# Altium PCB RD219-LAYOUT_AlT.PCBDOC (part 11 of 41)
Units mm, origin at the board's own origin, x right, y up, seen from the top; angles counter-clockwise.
Board outline 209.75 x 159.97 mm, 2 copper layers (TOP, BOTTOM), stack 0 mm thick; 398 components, 199 nets, 1469 pads, 0 vias.
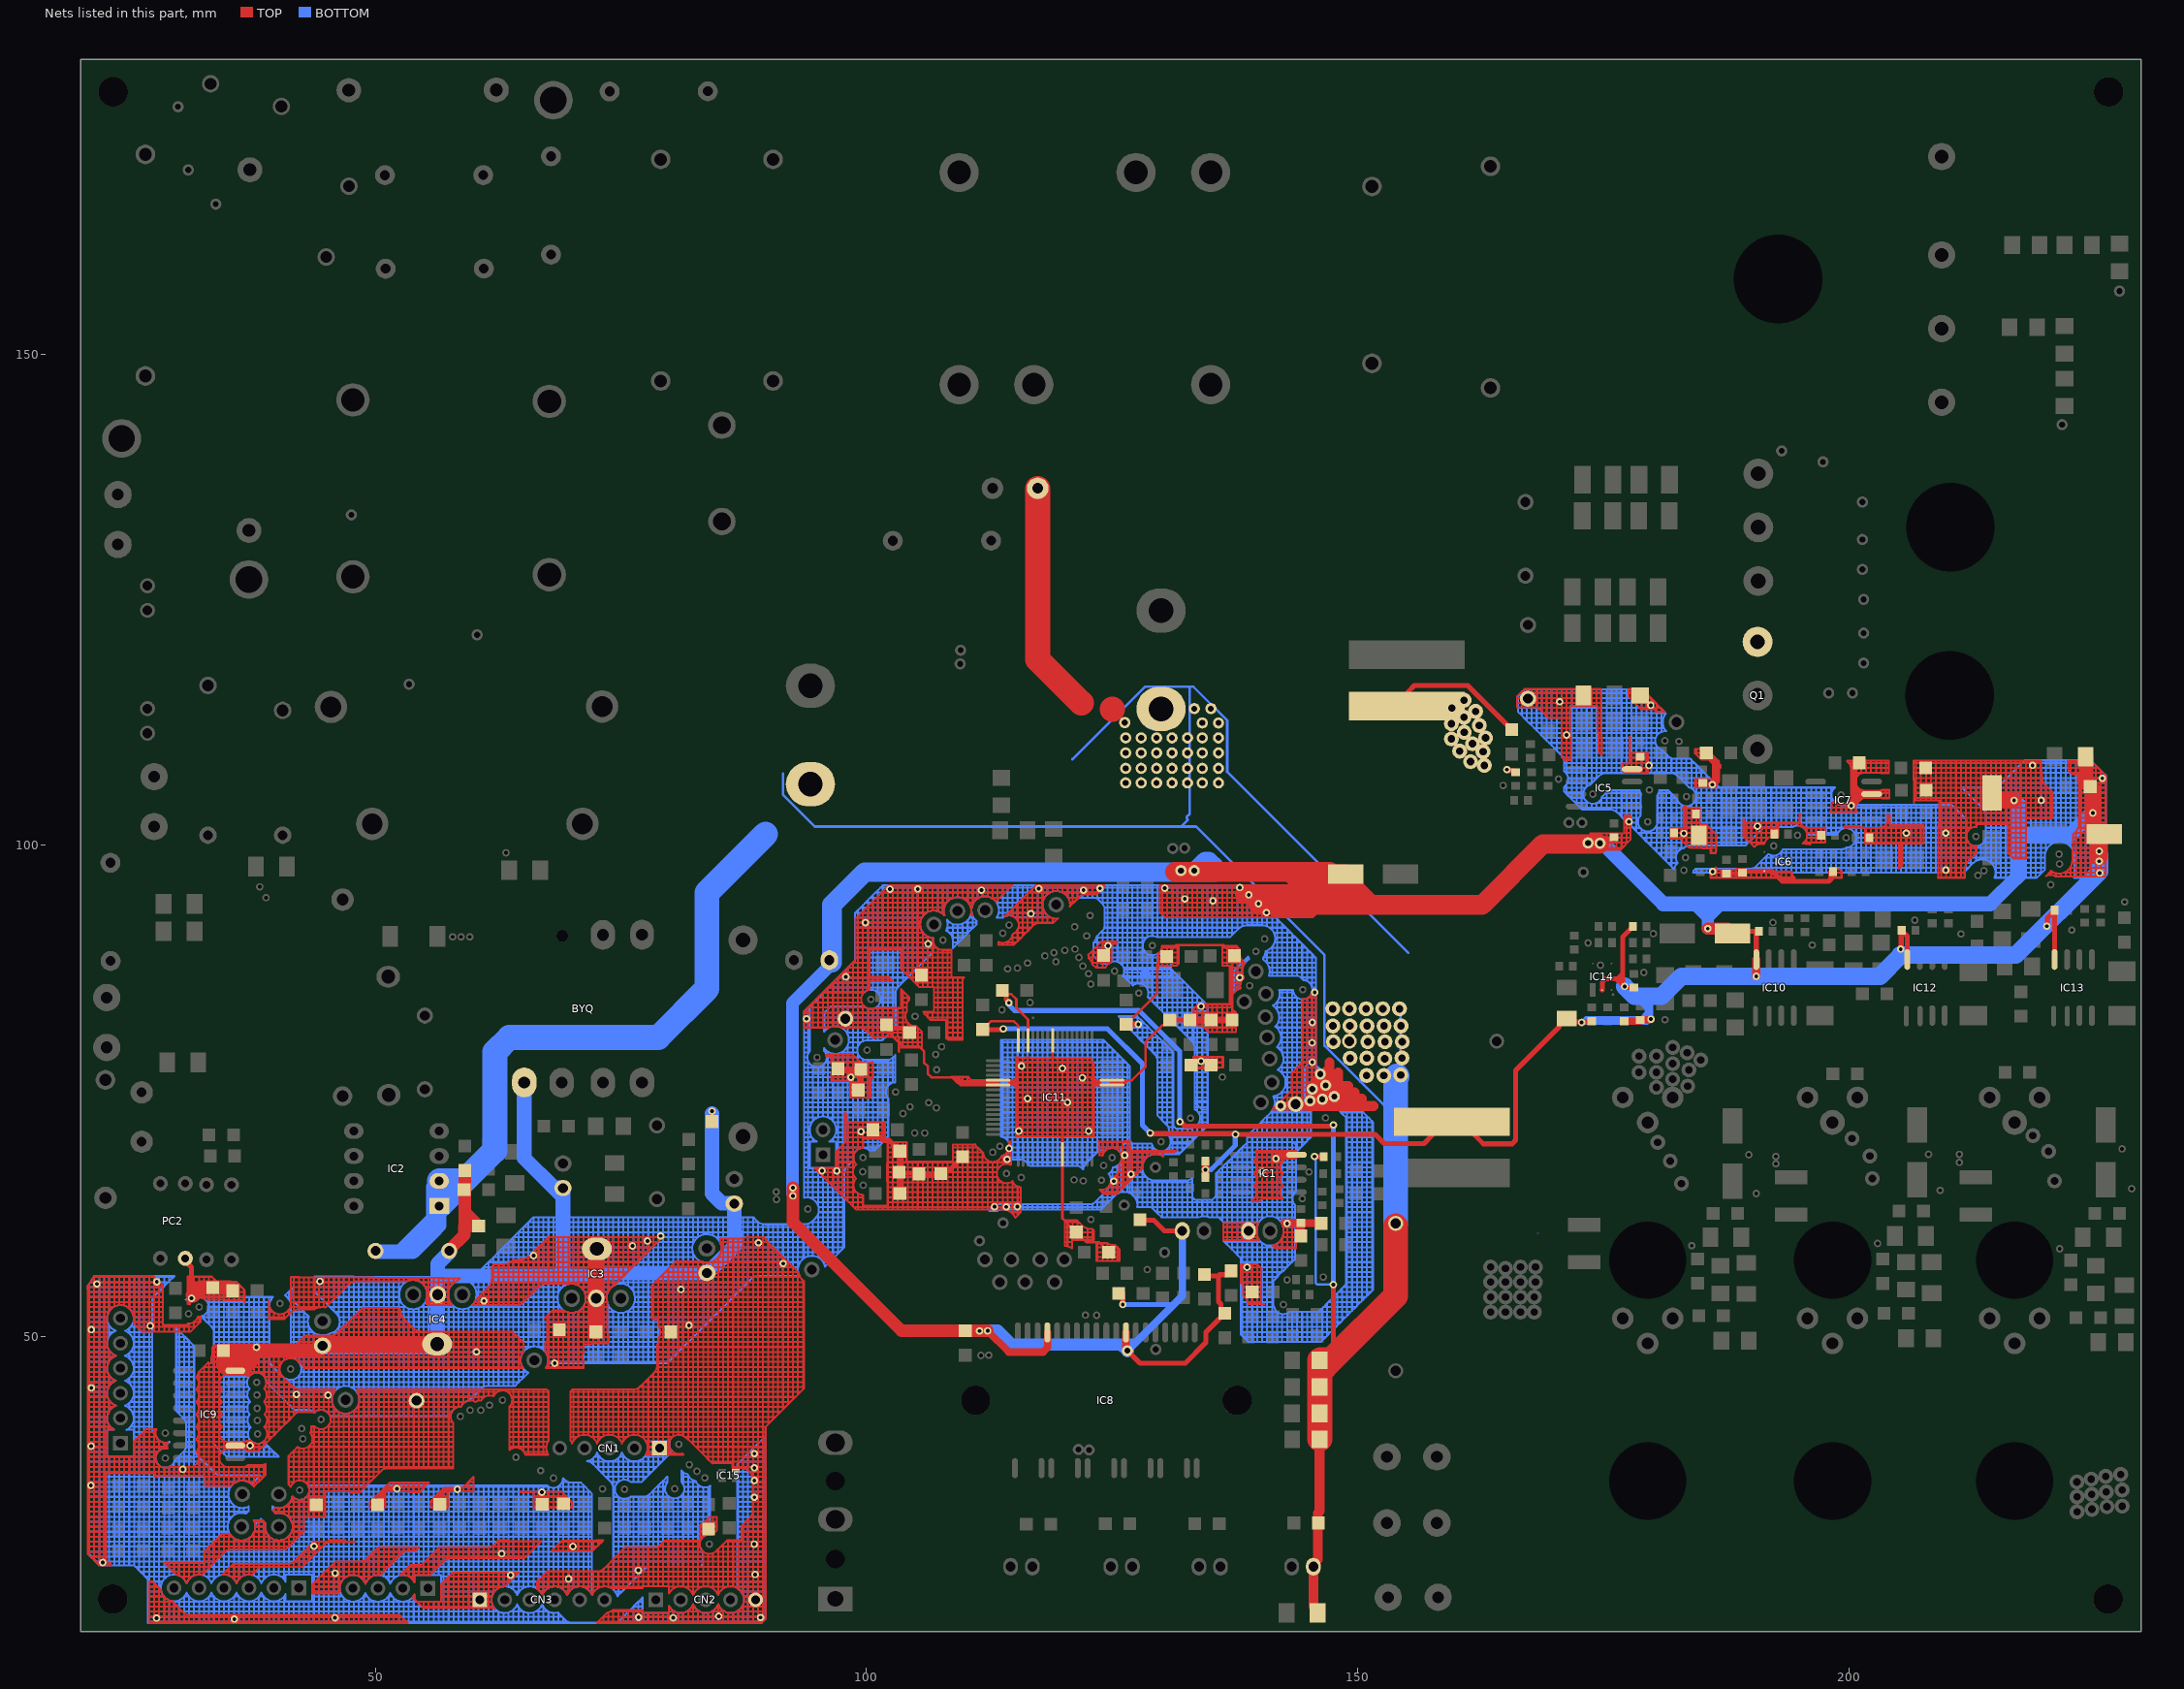
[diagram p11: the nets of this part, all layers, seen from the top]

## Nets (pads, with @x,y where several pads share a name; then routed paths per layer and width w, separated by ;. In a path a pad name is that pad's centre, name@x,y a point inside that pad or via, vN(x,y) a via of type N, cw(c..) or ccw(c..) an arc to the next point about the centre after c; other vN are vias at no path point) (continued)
GND: (continued)
  TOP w0.203: 84.897,55.56 84.897,56.068 ; 84.897,55.56 85.405,55.56 ; 84.897,56.068 84.897,56.576 ; 84.897,56.068 85.405,56.068 ; 84.897,56.576 84.897,57.084 ; 84.897,56.576 85.405,56.576 ; 84.897,57.084 84.897,57.592 ; 84.897,57.084 85.405,57.084 ; 84.897,57.592 85.405,57.592 ; 84.897,57.592 84.897,58.056 ; 84.897,58.056 ccw(c83.818,58.989) 84.934,58.1 ; 84.934,58.1 85.405,58.1 ; 84.999,28.469 85.165,28.636 ; 85.095,24.064 cw(c86.167,23.241) 85.102,24.073 cw(c86.167,23.241) 85.405,24.357 ; 85.106,59.624 85.106,59.914 85.193,60.001 85.405,60.001 ; 85.106,59.624 85.405,59.624 ; 85.165,28.636 85.405,28.636 ; 85.165,28.636 85.405,28.876 ; 85.239,59.116 85.405,59.116 ; 85.405,20.889 85.405,21.016 ; 85.405,20.889 85.913,20.889 ; 85.405,21.016 85.405,21.524 ; 85.405,21.016 85.913,21.016 ; 85.405,21.524 85.913,21.524 ; 85.405,21.524 85.405,22.032 ; 85.405,22.032 85.563,22.032 ; 85.405,24.357 cw(c86.167,23.241) 85.411,24.362 cw(c86.167,23.241) 85.913,24.569 ; 85.405,24.357 85.405,24.572 ; 85.405,24.572 85.913,24.572 ; 85.405,24.572 85.405,25.08 ; 85.405,25.08 85.913,25.08 ; 85.405,25.08 85.405,25.588 ; 85.405,25.588 85.405,26.096 ; 85.405,25.588 85.913,25.588 ; 85.405,26.096 85.913,26.096 ; 85.405,26.096 85.405,26.604 ; 85.405,26.604 85.405,27.112 ; 85.405,26.604 85.913,26.604 ; 85.405,27.112 85.405,27.62 ; 85.405,27.112 85.913,27.112 ; 85.405,27.62 85.405,28.128 ; 85.405,27.62 85.913,27.62 ; 85.405,28.128 85.405,28.636 ; 85.405,28.128 85.913,28.128 ; 85.405,28.636 85.405,28.876 ; 85.405,28.636 85.913,28.636 ; 85.405,28.876 85.673,29.144 ; 85.405,37.152 85.405,37.272 ; 85.405,37.152 85.913,37.152 ; 85.405,37.272 85.405,37.78 ; 85.405,37.272 85.913,37.272 ; 85.405,37.78 85.405,38.288 ; 85.405,37.78 85.913,37.78 ; 85.405,38.288 85.405,38.796 ; 85.405,38.288 85.913,38.288 ; 85.405,38.796 85.405,39.304 ; 85.405,38.796 85.913,38.796 ; 85.405,39.304 85.405,39.812 ; 85.405,39.304 85.913,39.304 ; 85.405,39.812 85.405,40.32 ; 85.405,39.812 85.913,39.812 ; 85.405,40.32 85.405,40.828 ; 85.405,40.32 85.913,40.32 ; 85.405,40.828 85.405,41.336 ; 85.405,40.828 85.913,40.828 ; 85.405,41.336 85.405,41.844 ; 85.405,41.336 85.913,41.336 ; 85.405,41.844 85.405,42.352 ; 85.405,41.844 85.913,41.844 ; 85.405,42.352 85.405,42.86 ; 85.405,42.352 85.913,42.352 ; 85.405,42.86 85.405,43.368 ; 85.405,42.86 85.913,42.86 ; 85.405,43.368 85.405,43.876 ; 85.405,43.368 85.913,43.368 ; 85.405,43.876 85.405,44.384 ; 85.405,43.876 85.913,43.876 ; 85.405,44.384 85.405,44.892 ; 85.405,44.384 85.913,44.384 ; 85.405,44.892 85.405,45.4 ; 85.405,44.892 85.913,44.892 ; 85.405,45.4 85.405,45.908 ; 85.405,45.4 85.913,45.4 ; 85.405,45.908 85.405,46.416 ; 85.405,45.908 85.913,45.908 ; 85.405,46.416 85.405,46.924 ; 85.405,46.416 85.913,46.416 ; 85.405,46.924 85.405,47.432 ; 85.405,46.924 85.913,46.924 ; 85.405,47.432 85.405,47.94 ; 85.405,47.432 85.913,47.432 ; 85.405,47.94 85.405,48.448 ; 85.405,47.94 85.913,47.94 ; 85.405,48.448 85.405,48.956 ; 85.405,48.448 85.913,48.448 ; 85.405,48.956 85.405,49.464 ; 85.405,48.956 85.913,48.956 ; 85.405,49.464 85.405,49.972 ; 85.405,49.464 85.913,49.464 ; 85.405,49.972 85.405,50.48 ; 85.405,49.972 85.913,49.972 ; 85.405,50.48 85.405,50.988 ; 85.405,50.48 85.913,50.48 ; 85.405,50.988 85.405,51.496 ; 85.405,50.988 85.913,50.988 ; 85.405,51.496 85.405,52.004 ; 85.405,51.496 85.913,51.496 ; 85.405,52.004 85.405,52.512 ; 85.405,52.004 85.913,52.004 ; 85.405,52.512 85.405,53.02 ; 85.405,52.512 85.913,52.512 ; 85.405,53.02 85.405,53.528 ; 85.405,53.02 85.913,53.02 ; 85.405,53.528 85.405,54.036 ; 85.405,53.528 85.913,53.528 ; 85.405,54.036 85.405,54.544 ; 85.405,54.036 85.913,54.036 ; 85.405,54.544 85.405,55.052 ; 85.405,54.544 85.913,54.544 ; 85.405,55.052 85.405,55.56 ; 85.405,55.052 85.913,55.052 ; 85.405,55.56 85.405,56.068 ; 85.405,55.56 85.913,55.56 ; 85.405,56.068 85.405,56.576 ; 85.405,56.068 85.913,56.068 ; 85.405,56.576 85.405,57.084 ; 85.405,56.576 85.913,56.576 ; 85.405,57.084 85.405,57.592 ; 85.405,57.084 85.913,57.084 ; 85.405,57.592 85.405,58.1 ; 85.405,57.592 85.913,57.592 ; 85.405,58.1 85.405,58.608 ; 85.405,58.1 85.913,58.1 ; 85.405,58.608 85.405,59.116 ; 85.405,58.608 85.913,58.608 ; 85.405,59.116 85.405,59.624 ; 85.405,59.116 85.913,59.116 ; 85.405,59.624 85.405,60.001 ; 85.405,59.624 85.913,59.624 ; 85.405,60.001 85.913,60.001 ; 85.563,22.032 ccw(c86.167,23.241) 85.909,21.914 ccw(c86.167,23.241) 85.913,21.914 ; 85.673,29.144 85.913,29.144 ; 85.673,29.144 85.833,29.303 85.913,29.303 ; 85.913,20.889 85.913,21.016 ; 85.913,20.889 86.421,20.889 ; 85.913,21.016 85.913,21.524 ; 85.913,21.016 86.421,21.016 ; 85.913,21.524 86.421,21.524 ; 85.913,21.524 85.913,21.913 ; 85.913,21.914 ccw(c86.167,23.241) 86.421,21.913 ; 85.913,24.569 cw(c86.167,23.241) 85.932,24.572 ; 85.913,24.569 85.913,24.572 ; 85.913,24.572 85.913,25.08 ; 85.913,24.572 85.932,24.572 ; 85.913,25.08 86.421,25.08 ; 85.913,25.08 85.913,25.588 ; 85.913,25.588 85.913,26.096 ; 85.913,25.588 86.421,25.588 ; 85.913,26.096 85.913,26.604 ; 85.913,26.096 86.421,26.096 ; 85.913,26.604 85.913,27.112 ; 85.913,26.604 86.421,26.604 ; 85.913,27.112 85.913,27.62 ; 85.913,27.112 86.421,27.112 ; 85.913,27.62 85.913,28.128 ; 85.913,27.62 86.421,27.62 ; 85.913,28.128 85.913,28.636 ; 85.913,28.128 86.421,28.128 ; 85.913,28.636 85.913,29.144 ; 85.913,28.636 86.421,28.636 ; 85.913,29.144 85.913,29.303 ; 85.913,29.144 86.421,29.144 ; 85.913,29.303 86.421,29.303 ; 85.913,37.152 85.913,37.272 ; 85.913,37.152 86.327,37.152 86.327,36.764 ; 85.913,37.272 85.913,37.78 ; 85.913,37.272 86.421,37.272 ; 85.913,37.78 85.913,38.288 ; 85.913,37.78 86.421,37.78 ; 85.913,38.288 85.913,38.796 ; 85.913,38.288 86.421,38.288 ; 85.913,38.796 85.913,39.304 ; 85.913,38.796 86.421,38.796 ; 85.913,39.304 85.913,39.812 ; 85.913,39.304 86.421,39.304 ; 85.913,39.812 86.421,39.812 ; 85.913,39.812 85.913,40.32 ; 85.913,40.32 85.913,40.828 ; 85.913,40.32 86.421,40.32 ; 85.913,40.828 85.913,41.336 ; 85.913,40.828 86.421,40.828 ; 85.913,41.336 85.913,41.844 ; 85.913,41.336 86.421,41.336 ; 85.913,41.844 85.913,42.352 ; 85.913,41.844 86.421,41.844 ; 85.913,42.352 85.913,42.86 ; 85.913,42.352 86.421,42.352 ; 85.913,42.86 85.913,43.368 ; 85.913,42.86 86.421,42.86 ; 85.913,43.368 85.913,43.876 ; 85.913,43.368 86.421,43.368 ; 85.913,43.876 85.913,44.384 ; 85.913,43.876 86.421,43.876 ; 85.913,44.384 86.421,44.384 ; 85.913,44.384 85.913,44.892 ; 85.913,44.892 86.421,44.892 ; 85.913,44.892 85.913,45.4 ; 85.913,45.4 85.913,45.908 ; 85.913,45.4 86.421,45.4 ; 85.913,45.908 85.913,46.416 ; 85.913,45.908 86.421,45.908 ; 85.913,46.416 86.421,46.416 ; 85.913,46.416 85.913,46.924 ; 85.913,46.924 86.421,46.924 ; 85.913,46.924 85.913,47.432 ; 85.913,47.432 85.913,47.94 ; 85.913,47.432 86.421,47.432 ; 85.913,47.94 85.913,48.448 ; 85.913,47.94 86.421,47.94 ; 85.913,48.448 85.913,48.956 ; 85.913,48.448 86.421,48.448 ; 85.913,48.956 85.913,49.464 ; 85.913,48.956 86.421,48.956 ; 85.913,49.464 85.913,49.972 ; 85.913,49.464 86.421,49.464 ; 85.913,49.972 86.421,49.972 ; 85.913,49.972 85.913,50.48 ; 85.913,50.48 85.913,50.988 ; 85.913,50.48 86.421,50.48 ; 85.913,50.988 86.421,50.988 ; 85.913,50.988 85.913,51.496 ; 85.913,51.496 85.913,52.004 ; 85.913,51.496 86.421,51.496 ; 85.913,52.004 86.421,52.004 ; 85.913,52.004 85.913,52.512 ; 85.913,52.512 85.913,53.02 ; 85.913,52.512 86.421,52.512 ; 85.913,53.02 86.421,53.02 ; 85.913,53.02 85.913,53.528 ; 85.913,53.528 85.913,54.036 ; 85.913,53.528 86.421,53.528 ; 85.913,54.036 85.913,54.544 ; 85.913,54.036 86.421,54.036 ; 85.913,54.544 85.913,55.052 ; 85.913,54.544 86.421,54.544 ; 85.913,55.052 86.421,55.052 ; 85.913,55.052 85.913,55.56 ; 85.913,55.56 86.421,55.56 ; 85.913,55.56 85.913,56.068 ; 85.913,56.068 85.913,56.576 ; 85.913,56.068 86.421,56.068 ; 85.913,56.576 86.421,56.576 ; 85.913,56.576 85.913,57.084 ; 85.913,57.084 85.913,57.592 ; 85.913,57.084 86.421,57.084 ; 85.913,57.592 85.913,58.1 ; 85.913,57.592 86.421,57.592 ; 85.913,58.1 85.913,58.608 ; 85.913,58.1 86.421,58.1 ; 85.913,58.608 85.913,59.116 ; 85.913,58.608 86.421,58.608 ; 85.913,59.116 86.421,59.116 ; 85.913,59.116 85.913,59.624 ; 85.913,59.624 86.421,59.624 ; 85.913,59.624 85.913,60.001 ; 85.913,60.001 86.421,60.001 ; 85.932,24.572 cw(c86.167,23.241) 86.402,24.572 ; 86.327,36.764 86.421,36.764 ; 86.327,36.764 86.327,36.652 86.421,36.652 ; 86.402,24.572 cw(c86.167,23.241) 86.421,24.569 ; 86.402,24.572 86.421,24.572 ; 86.421,20.889 86.421,21.016 ; 86.421,20.889 86.929,20.889 ; 86.421,21.016 86.421,21.524 ; 86.421,21.016 86.929,21.016 ; 86.421,21.524 86.929,21.524 ; 86.421,21.524 86.421,21.913 ; 86.421,21.913 ccw(c86.167,23.241) 86.425,21.914 ccw(c86.167,23.241) 86.771,22.032 ; 86.421,24.569 cw(c86.167,23.241) 86.425,24.568 cw(c86.167,23.241) 86.923,24.362 cw(c86.167,23.241) 86.929,24.357 ; 86.421,24.569 86.421,24.572 ; 86.421,24.572 86.929,24.572 ; 86.421,24.572 86.421,25.08 ; 86.421,25.08 86.421,25.588 ; 86.421,25.08 86.929,25.08 ; 86.421,25.588 86.421,26.096 ; 86.421,25.588 86.929,25.588 ; 86.421,26.096 86.421,26.604 ; 86.421,26.096 86.929,26.096 ; 86.421,26.604 86.421,27.112 ; 86.421,26.604 86.929,26.604 ; 86.421,27.112 86.421,27.62 ; 86.421,27.112 86.929,27.112 ; 86.421,27.62 86.421,28.128 ; 86.421,27.62 86.929,27.62 ; 86.421,28.128 86.421,28.636 ; 86.421,28.128 86.929,28.128 ; 86.421,28.636 86.421,29.144 ; 86.421,28.636 86.929,28.636 ; 86.421,29.144 86.421,29.303 ; 86.421,29.144 86.929,29.144 ; 86.421,29.303 86.929,29.303 ; 86.421,36.652 86.675,36.652 86.929,36.652 ; 86.421,36.652 86.421,36.764 ; 86.421,36.764 86.929,36.764 ; 86.421,36.764 86.421,37.272 ; 86.421,37.272 86.421,37.78 ; 86.421,37.272 86.929,37.272 ; 86.421,37.78 86.421,38.288 ; 86.421,37.78 86.929,37.78 ; 86.421,38.288 86.421,38.796 ; 86.421,38.288 86.929,38.288 ; 86.421,38.796 86.421,39.304 ; 86.421,38.796 86.929,38.796 ; 86.421,39.304 86.421,39.812 ; 86.421,39.304 86.929,39.304 ; 86.421,39.812 86.929,39.812 ; 86.421,39.812 86.421,40.32 ; 86.421,40.32 86.421,40.828 ; 86.421,40.32 86.929,40.32 ; 86.421,40.828 86.421,41.336 ; 86.421,40.828 86.929,40.828 ; 86.421,41.336 86.421,41.844 ; 86.421,41.336 86.929,41.336 ; 86.421,41.844 86.421,42.352 ; 86.421,41.844 86.929,41.844 ; 86.421,42.352 86.421,42.86 ; 86.421,42.352 86.929,42.352 ; 86.421,42.86 86.421,43.368 ; 86.421,42.86 86.929,42.86 ; 86.421,43.368 86.421,43.876 ; 86.421,43.368 86.929,43.368 ; 86.421,43.876 86.421,44.384 ; 86.421,43.876 86.929,43.876 ; 86.421,44.384 86.421,44.892 ; 86.421,44.384 86.929,44.384 ; 86.421,44.892 86.421,45.4 ; 86.421,44.892 86.929,44.892 ; 86.421,45.4 86.421,45.908 ; 86.421,45.4 86.929,45.4 ; 86.421,45.908 86.421,46.416 ; 86.421,45.908 86.929,45.908 ; 86.421,46.416 86.421,46.924 ; 86.421,46.416 86.929,46.416 ; 86.421,46.924 86.421,47.432 ; 86.421,46.924 86.929,46.924 ; 86.421,47.432 86.421,47.94 ; 86.421,47.432 86.929,47.432 ; 86.421,47.94 86.421,48.448 ; 86.421,47.94 86.929,47.94 ; 86.421,48.448 86.421,48.956 ; 86.421,48.448 86.929,48.448 ; 86.421,48.956 86.421,49.464 ; 86.421,48.956 86.929,48.956 ; 86.421,49.464 86.421,49.972 ; 86.421,49.464 86.929,49.464 ; 86.421,49.972 86.421,50.48 ; 86.421,49.972 86.929,49.972 ; 86.421,50.48 86.421,50.988 ; 86.421,50.48 86.929,50.48 ; 86.421,50.988 86.421,51.496 ; 86.421,50.988 86.929,50.988 ; 86.421,51.496 86.421,52.004 ; 86.421,51.496 86.929,51.496 ; 86.421,52.004 86.421,52.512 ; 86.421,52.004 86.929,52.004 ; 86.421,52.512 86.421,53.02 ; 86.421,52.512 86.929,52.512 ; 86.421,53.02 86.421,53.528 ; 86.421,53.02 86.929,53.02 ; 86.421,53.528 86.421,54.036 ; 86.421,53.528 86.929,53.528 ; 86.421,54.036 86.421,54.544 ; 86.421,54.036 86.929,54.036 ; 86.421,54.544 86.421,55.052 ; 86.421,54.544 86.929,54.544 ; 86.421,55.052 86.421,55.56 ; 86.421,55.052 86.929,55.052 ; 86.421,55.56 86.421,56.068 ; 86.421,55.56 86.929,55.56 ; 86.421,56.068 86.421,56.576 ; 86.421,56.068 86.929,56.068 ; 86.421,56.576 86.421,57.084 ; 86.421,56.576 86.929,56.576 ; 86.421,57.084 86.421,57.592 ; 86.421,57.084 86.929,57.084 ; 86.421,57.592 86.421,58.1 ; 86.421,57.592 86.929,57.592 ; 86.421,58.1 86.421,58.608 ; 86.421,58.1 86.929,58.1 ; 86.421,58.608 86.421,59.116 ; 86.421,58.608 86.929,58.608 ; 86.421,59.116 86.421,59.624 ; 86.421,59.116 86.929,59.116 ; 86.421,59.624 86.421,60.001 ; 86.421,59.624 86.929,59.624 ; 86.421,60.001 86.929,60.001 ; 86.771,22.032 ccw(c86.167,23.241) 86.923,22.12 ccw(c86.167,23.241) 86.929,22.125 ; 86.771,22.032 86.929,22.032 ; 86.929,20.889 86.929,21.016 ; 86.929,20.889 87.437,20.889 ; 86.929,21.016 86.929,21.524 ; 86.929,21.016 87.437,21.016 ; 86.929,21.524 86.929,22.032 ; 86.929,21.524 87.437,21.524 ; 86.929,22.032 87.437,22.032 ; 86.929,22.032 86.929,22.125 ; 86.929,24.357 86.929,24.572 ; 86.929,24.572 86.929,25.08 ; 86.929,24.572 87.437,24.572 ; 86.929,25.08 86.929,25.588 ; 86.929,25.08 87.437,25.08 ; 86.929,25.588 86.929,26.096 ; 86.929,25.588 87.437,25.588 ; 86.929,26.096 86.929,26.604 ; 86.929,26.096 87.437,26.096 ; 86.929,26.604 86.929,27.112 ; 86.929,26.604 87.437,26.604 ; 86.929,27.112 86.929,27.62 ; 86.929,27.112 87.437,27.112 ; 86.929,27.62 86.929,28.128 ; 86.929,27.62 87.437,27.62 ; 86.929,28.128 86.929,28.636 ; 86.929,28.128 87.437,28.128 ; 86.929,28.636 86.929,29.144 ; 86.929,28.636 87.437,28.636 ; 86.929,29.144 86.929,29.303 ; 86.929,29.144 87.437,29.144 ; 86.929,29.303 87.279,29.303 87.279,29.652 ; 86.929,36.652 86.929,36.764 ; 86.929,36.652 87.437,36.652 ; 86.929,36.764 87.437,36.764 ; 86.929,36.764 86.929,37.272 ; 86.929,37.272 86.929,37.78 ; 86.929,37.272 87.437,37.272 ; 86.929,37.78 86.929,38.288 ; 86.929,37.78 87.437,37.78 ; 86.929,38.288 86.929,38.796 ; 86.929,38.288 87.437,38.288 ; 86.929,38.796 86.929,39.304 ; 86.929,38.796 87.437,38.796 ; 86.929,39.304 86.929,39.812 ; 86.929,39.304 87.437,39.304 ; 86.929,39.812 86.929,40.32 ; 86.929,39.812 87.437,39.812 ; 86.929,40.32 86.929,40.828 ; 86.929,40.32 87.437,40.32 ; 86.929,40.828 86.929,41.336 ; 86.929,40.828 87.437,40.828 ; 86.929,41.336 86.929,41.844 ; 86.929,41.336 87.437,41.336 ; 86.929,41.844 86.929,42.352 ; 86.929,41.844 87.437,41.844 ; 86.929,42.352 86.929,42.86 ; 86.929,42.352 87.437,42.352 ; 86.929,42.86 86.929,43.368 ; 86.929,42.86 87.437,42.86 ; 86.929,43.368 86.929,43.876 ; 86.929,43.368 87.437,43.368 ; 86.929,43.876 86.929,44.384 ; 86.929,43.876 87.437,43.876 ; 86.929,44.384 86.929,44.892 ; 86.929,44.384 87.437,44.384 ; 86.929,44.892 86.929,45.4 ; 86.929,44.892 87.437,44.892 ; 86.929,45.4 86.929,45.908 ; 86.929,45.4 87.437,45.4 ; 86.929,45.908 86.929,46.416 ; 86.929,45.908 87.437,45.908 ; 86.929,46.416 86.929,46.924 ; 86.929,46.416 87.437,46.416 ; 86.929,46.924 86.929,47.432 ; 86.929,46.924 87.437,46.924 ; 86.929,47.432 86.929,47.94 ; 86.929,47.432 87.437,47.432 ; 86.929,47.94 86.929,48.448 ; 86.929,47.94 87.437,47.94 ; 86.929,48.448 86.929,48.956 ; 86.929,48.448 87.437,48.448 ; 86.929,48.956 86.929,49.464 ; 86.929,48.956 87.437,48.956 ; 86.929,49.464 86.929,49.972 ; 86.929,49.464 87.437,49.464 ; 86.929,49.972 86.929,50.48 ; 86.929,49.972 87.437,49.972 ; 86.929,50.48 86.929,50.988 ; 86.929,50.48 87.437,50.48 ; 86.929,50.988 86.929,51.496 ; 86.929,50.988 87.437,50.988 ; 86.929,51.496 86.929,52.004 ; 86.929,51.496 87.437,51.496 ; 86.929,52.004 86.929,52.512 ; 86.929,52.004 87.437,52.004 ; 86.929,52.512 86.929,53.02 ; 86.929,52.512 87.437,52.512 ; 86.929,53.02 86.929,53.528 ; 86.929,53.02 87.437,53.02 ; 86.929,53.528 86.929,54.036 ; 86.929,53.528 87.437,53.528 ; 86.929,54.036 86.929,54.544 ; 86.929,54.036 87.437,54.036 ; 86.929,54.544 86.929,55.052 ; 86.929,54.544 87.437,54.544 ; 86.929,55.052 86.929,55.56 ; 86.929,55.052 87.437,55.052 ; 86.929,55.56 86.929,56.068 ; 86.929,55.56 87.437,55.56 ; 86.929,56.068 86.929,56.576 ; 86.929,56.068 87.437,56.068 ; 86.929,56.576 86.929,57.084 ; 86.929,56.576 87.437,56.576 ; 86.929,57.084 86.929,57.592 ; 86.929,57.084 87.437,57.084 ; 86.929,57.592 86.929,58.1 ; 86.929,57.592 87.437,57.592 ; 86.929,58.1 86.929,58.608 ; 86.929,58.1 87.437,58.1 ; 86.929,58.608 86.929,59.116 ; 86.929,58.608 87.437,58.608 ; 86.929,59.116 86.929,59.624 ; 86.929,59.116 87.437,59.116 ; 86.929,59.624 86.929,60.001 ; 86.929,59.624 87.437,59.624 ; 86.929,60.001 87.202,60.001 ; 87.202,60.001 ccw(c87.202,61.353) 87.437,60.022 ; 87.202,60.001 ccw(c87.202,61.353) 87.437,60.022 ; 87.279,29.652 87.437,29.652 ; 87.279,29.652 87.279,30.16 ; 87.279,30.16 87.279,30.668 ; 87.279,30.16 87.437,30.16 ; 87.279,30.668 87.279,30.749 87.437,30.908 ; 87.279,30.668 87.437,30.668 ; 87.437,20.889 87.437,21.016 ; 87.437,20.889 87.945,20.889 ; 87.437,21.016 87.437,21.524 ; 87.437,21.016 87.945,21.016 ; 87.437,21.524 87.437,22.032 ; 87.437,21.524 87.945,21.524 ; 87.437,22.032 87.437,22.54 ; 87.437,22.032 87.945,22.032 ; 87.437,22.54 87.945,22.54 ; 87.437,22.54 87.437,22.778 ; 87.437,22.779 ccw(c86.167,23.241) 87.505,23.048 ; 87.437,23.704 cw(c86.167,23.241) 87.481,23.556 ; 87.437,23.704 87.437,24.064 ; 87.437,24.064 87.437,24.572 ; 87.437,24.064 87.945,24.064 ; 87.437,24.572 87.437,25.08 ; 87.437,24.572 87.945,24.572 ; 87.437,25.08 87.437,25.588 ; 87.437,25.08 87.945,25.08 ; 87.437,25.588 87.437,26.096 ; 87.437,25.588 87.945,25.588 ; 87.437,26.096 87.437,26.604 ; 87.437,26.096 87.945,26.096 ; 87.437,26.604 87.437,27.112 ; 87.437,26.604 87.945,26.604 ; 87.437,27.112 87.437,27.62 ; 87.437,27.112 87.945,27.112 ; 87.437,27.62 87.437,28.128 ; 87.437,27.62 87.945,27.62 ; 87.437,28.128 87.437,28.636 ; 87.437,28.128 87.945,28.128 ; 87.437,28.636 87.437,29.144 ; 87.437,28.636 87.945,28.636 ; 87.437,29.144 87.437,29.652 ; 87.437,29.144 87.945,29.144 ; 87.437,29.652 87.437,30.16 ; 87.437,29.652 87.945,29.652 ; 87.437,30.16 87.437,30.668 ; 87.437,30.16 87.945,30.16 ; 87.437,30.668 87.437,30.908 ; 87.437,30.668 87.945,30.668 ; 87.437,30.908 87.705,31.176 ; 87.437,36.652 87.437,36.764 ; 87.437,36.652 87.677,36.652 87.677,36.544 ; 87.437,36.764 87.437,37.272 ; 87.437,36.764 87.945,36.764 ; 87.437,37.272 87.437,37.78 ; 87.437,37.272 87.945,37.272 ; 87.437,37.78 87.437,38.288 ; 87.437,37.78 87.945,37.78 ; 87.437,38.288 87.437,38.796 ; 87.437,38.288 87.945,38.288 ; 87.437,38.796 87.437,39.304 ; 87.437,38.796 87.945,38.796 ; 87.437,39.304 87.437,39.812 ; 87.437,39.304 87.945,39.304 ; 87.437,39.812 87.437,40.32 ; 87.437,39.812 87.945,39.812 ; 87.437,40.32 87.437,40.828 ; 87.437,40.32 87.945,40.32 ; 87.437,40.828 87.437,41.336 ; 87.437,40.828 87.945,40.828 ; 87.437,41.336 87.437,41.844 ; 87.437,41.336 87.945,41.336 ; 87.437,41.844 87.437,42.352 ; 87.437,41.844 87.945,41.844 ; 87.437,42.352 87.437,42.86 ; 87.437,42.352 87.945,42.352 ; 87.437,42.86 87.437,43.368 ; 87.437,42.86 87.945,42.86 ; 87.437,43.368 87.437,43.876 ; 87.437,43.368 87.945,43.368 ; 87.437,43.876 87.437,44.384 ; 87.437,43.876 87.945,43.876 ; 87.437,44.384 87.437,44.892 ; 87.437,44.384 87.945,44.384 ; 87.437,44.892 87.437,45.4 ; 87.437,44.892 87.945,44.892 ; 87.437,45.4 87.437,45.908 ; 87.437,45.4 87.945,45.4 ; 87.437,45.908 87.437,46.416 ; 87.437,45.908 87.945,45.908 ; 87.437,46.416 87.437,46.924 ; 87.437,46.416 87.945,46.416 ; 87.437,46.924 87.437,47.432 ; 87.437,46.924 87.945,46.924 ; 87.437,47.432 87.437,47.94 ; 87.437,47.432 87.945,47.432 ; 87.437,47.94 87.437,48.448 ; 87.437,47.94 87.945,47.94 ; 87.437,48.448 87.437,48.956 ; 87.437,48.448 87.945,48.448 ; 87.437,48.956 87.437,49.464 ; 87.437,48.956 87.945,48.956 ; 87.437,49.464 87.437,49.972 ; 87.437,49.464 87.945,49.464 ; 87.437,49.972 87.437,50.48 ; 87.437,49.972 87.945,49.972 ; 87.437,50.48 87.437,50.988 ; 87.437,50.48 87.945,50.48 ; 87.437,50.988 87.437,51.496 ; 87.437,50.988 87.945,50.988 ; 87.437,51.496 87.437,52.004 ; 87.437,51.496 87.945,51.496 ; 87.437,52.004 87.437,52.512 ; 87.437,52.004 87.945,52.004 ; 87.437,52.512 87.437,53.02 ; 87.437,52.512 87.945,52.512 ; 87.437,53.02 87.437,53.528 ; 87.437,53.02 87.945,53.02 ; 87.437,53.528 87.437,54.036 ; 87.437,53.528 87.945,53.528 ; 87.437,54.036 87.437,54.544 ; 87.437,54.036 87.945,54.036 ; 87.437,54.544 87.437,55.052 ; 87.437,54.544 87.945,54.544 ; 87.437,55.052 87.437,55.56 ; 87.437,55.052 87.945,55.052 ; 87.437,55.56 87.437,56.068 ; 87.437,55.56 87.945,55.56 ; 87.437,56.068 87.437,56.576 ; 87.437,56.068 87.945,56.068 ; 87.437,56.576 87.437,57.084 ; 87.437,56.576 87.945,56.576 ; 87.437,57.084 87.437,57.592 ; 87.437,57.084 87.945,57.084 ; 87.437,57.592 87.437,58.1 ; 87.437,57.592 87.945,57.592 ; 87.437,58.1 87.437,58.608 ; 87.437,58.1 87.945,58.1 ; 87.437,58.608 87.437,59.116 ; 87.437,58.608 87.945,58.608 ; 87.437,59.116 87.437,59.624 ; 87.437,59.116 87.945,59.116 ; 87.437,59.624 87.945,59.624 ; 87.437,59.624 87.437,60.022 ; 87.437,60.022 ccw(c87.202,61.353) 87.774,60.128 cw(c87.202,61.353) 87.437,60.022 ; 87.481,23.556 cw(c86.167,23.241) 87.484,23.545 cw(c86.167,23.241) 87.519,23.241 cw(c86.167,23.241) 87.505,23.048 ; 87.481,23.556 87.945,23.556 ; 87.505,23.048 87.945,23.048 ; 87.677,36.544 cw(c87.465,35.847) 87.678,36.544 ; 87.677,36.544 cw(c87.465,35.847) 87.678,36.544 ; 87.677,36.544 ccw(c87.465,35.847) 87.465,36.576 cw(c87.465,35.847) 87.677,36.544 ; 87.678,36.544 cw(c87.465,35.847) 87.945,36.395 ; 87.678,36.544 cw(c87.465,35.847) 87.945,36.395 ; 87.705,31.176 87.945,31.176 ; 87.705,31.176 87.945,31.416 ; 87.945,20.889 87.945,21.016 ; 87.945,20.889 88.453,20.889 ; 87.945,21.016 87.945,21.524 ; 87.945,21.016 88.453,21.016 ; 87.945,21.524 87.945,22.032 ; 87.945,21.524 88.453,21.524 ; 87.945,22.032 87.945,22.54 ; 87.945,22.032 88.453,22.032 ; 87.945,22.54 87.945,23.048 ; 87.945,22.54 CN2.5@88.453,22.54 ; 87.945,23.048 CN2.5@88.453,23.048 ; 87.945,23.048 87.945,23.556 ; 87.945,23.556 87.945,24.064 ; 87.945,23.556 CN2.5@88.453,23.556 ; 87.945,24.064 87.945,24.572 ; 87.945,24.064 88.453,24.064 ; 87.945,24.572 87.945,25.08 ; 87.945,24.572 88.453,24.572 ; 87.945,25.08 87.945,25.588 ; 87.945,25.08 88.453,25.08 ; 87.945,25.588 87.945,26.096 ; 87.945,25.588 pad.@88.453,25.588 ; 87.945,26.096 87.945,26.604 ; 87.945,26.096 pad.@88.453,26.096 ; 87.945,26.604 87.945,27.112 ; 87.945,26.604 88.453,26.604 ; 87.945,27.112 87.945,27.62 ; 87.945,27.112 88.453,27.112 ; 87.945,27.62 87.945,28.128 ; 87.945,27.62 88.453,27.62 ; 87.945,28.128 87.945,28.636 ; 87.945,28.128 88.453,28.128 ; 87.945,28.636 87.945,29.144 ; 87.945,28.636 pad.@88.453,28.636 ; 87.945,29.144 87.945,29.652 ; 87.945,29.144 pad.@88.453,29.144 ; 87.945,29.652 87.945,30.16 ; 87.945,29.652 88.453,29.652 ; 87.945,30.16 87.945,30.668 ; 87.945,30.16 88.453,30.16 ; 87.945,30.668 87.945,31.176 ; 87.945,30.668 88.453,30.668 ; 87.945,31.176 87.945,31.416 ; 87.945,31.176 88.453,31.176 ; 87.945,31.416 88.206,31.677 ; 87.945,36.395 cw(c87.465,35.847) 87.98,36.362 ; 87.945,36.395 cw(c87.465,35.847) 87.98,36.362 ; 87.945,36.395 87.945,36.764 ; 87.945,36.764 87.945,37.272 ; 87.945,36.764 pad.@88.453,36.764 ; 87.945,37.272 87.945,37.78 ; 87.945,37.272 88.453,37.272 ; 87.945,37.78 87.945,38.288 ; 87.945,37.78 pad.@88.453,37.78 ; 87.945,38.288 87.945,38.796 ; 87.945,38.288 pad.@88.453,38.288 ; 87.945,38.796 87.945,39.304 ; 87.945,38.796 88.453,38.796 ; 87.945,39.304 87.945,39.812 ; 87.945,39.304 88.453,39.304 ; 87.945,39.812 87.945,40.32 ; 87.945,39.812 88.453,39.812 ; 87.945,40.32 87.945,40.828 ; 87.945,40.32 88.453,40.32 ; 87.945,40.828 87.945,41.336 ; 87.945,40.828 88.453,40.828 ; 87.945,41.336 87.945,41.844 ; 87.945,41.336 88.453,41.336 ; 87.945,41.844 87.945,42.352 ; 87.945,41.844 88.453,41.844 ; 87.945,42.352 87.945,42.86 ; 87.945,42.352 88.453,42.352 ; 87.945,42.86 87.945,43.368 ; 87.945,42.86 88.453,42.86 ; 87.945,43.368 87.945,43.876 ; 87.945,43.368 88.453,43.368 ; 87.945,43.876 87.945,44.384 ; 87.945,43.876 88.453,43.876 ; 87.945,44.384 87.945,44.892 ; 87.945,44.384 88.453,44.384 ; 87.945,44.892 87.945,45.4 ; 87.945,44.892 88.453,44.892 ; 87.945,45.4 87.945,45.908 ; 87.945,45.4 88.453,45.4 ; 87.945,45.908 87.945,46.416 ; 87.945,45.908 88.453,45.908 ; 87.945,46.416 87.945,46.924 ; 87.945,46.416 88.453,46.416 ; 87.945,46.924 87.945,47.432 ; 87.945,46.924 88.453,46.924 ; 87.945,47.432 87.945,47.94 ; 87.945,47.432 88.453,47.432 ; 87.945,47.94 87.945,48.448 ; 87.945,47.94 88.453,47.94 ; 87.945,48.448 87.945,48.956 ; 87.945,48.448 88.453,48.448 ; 87.945,48.956 87.945,49.464 ; 87.945,48.956 88.453,48.956 ; 87.945,49.464 87.945,49.972 ; 87.945,49.464 88.453,49.464 ; 87.945,49.972 87.945,50.48 ; 87.945,49.972 88.453,49.972 ; 87.945,50.48 87.945,50.988 ; 87.945,50.48 88.453,50.48 ; 87.945,50.988 87.945,51.496 ; 87.945,50.988 88.453,50.988 ; 87.945,51.496 87.945,52.004 ; 87.945,51.496 88.453,51.496 ; 87.945,52.004 87.945,52.512 ; 87.945,52.004 88.453,52.004 ; 87.945,52.512 87.945,53.02 ; 87.945,52.512 88.453,52.512 ; 87.945,53.02 87.945,53.528 ; 87.945,53.02 88.453,53.02 ; 87.945,53.528 87.945,54.036 ; 87.945,53.528 88.453,53.528 ; 87.945,54.036 87.945,54.544 ; 87.945,54.036 88.453,54.036 ; 87.945,54.544 87.945,55.052 ; 87.945,54.544 88.453,54.544 ; 87.945,55.052 87.945,55.56 ; 87.945,55.052 88.453,55.052 ; 87.945,55.56 87.945,56.068 ; 87.945,55.56 88.453,55.56 ; 87.945,56.068 87.945,56.576 ; 87.945,56.068 88.453,56.068 ; 87.945,56.576 87.945,57.084 ; 87.945,56.576 88.453,56.576 ; 87.945,57.084 87.945,57.592 ; 87.945,57.084 88.453,57.084 ; 87.945,57.592 87.945,58.1 ; 87.945,57.592 88.453,57.592 ; 87.945,58.1 87.945,58.608 ; 87.945,58.1 88.453,58.1 ; 87.945,58.608 87.945,59.116 ; 87.945,58.608 88.453,58.608 ; 87.945,59.116 87.945,59.624 ; 87.945,59.116 88.453,59.116 ; 87.945,59.624 87.945,60.132 ; 87.945,59.624 88.453,59.624 ; 87.945,60.132 88.453,60.132 ; 87.98,36.362 88.086,36.256 ; 88.086,36.256 88.453,36.256 ; 88.086,36.256 88.206,36.136 ; 88.206,31.677 ccw(c87.691,32.192) 88.213,31.684 ; 88.206,31.677 ccw(c87.691,32.192) 88.213,31.684 ; 88.206,36.136 cw(c87.691,35.621) 88.408,35.748 ; 88.206,36.136 cw(c87.691,35.621) 88.408,35.748 ; 88.213,31.684 ccw(c87.691,32.192) 88.295,31.785 ccw(c87.691,32.192) 88.42,32.192 ; 88.213,31.684 ccw(c87.691,32.192) 88.42,32.192 ; 88.213,31.684 88.453,31.684 ; 88.408,35.748 cw(c87.691,35.621) pad.@88.42,35.621 ; 88.408,35.748 cw(c87.691,35.621) pad.@88.42,35.621 ; 88.408,35.748 88.453,35.748 ; 88.42,32.192 88.453,32.192 ; 88.42,32.192 88.42,32.7 ; 88.42,32.7 88.453,32.7 ; 88.42,32.7 88.42,33.208 ; 88.42,33.208 88.453,33.208 ; 88.42,33.208 pad.@88.42,33.716 ; pad.@88.42,33.716 pad.@88.453,33.716 ; pad.@88.42,33.716 88.42,34.224 ; 88.42,34.224 88.453,34.224 ; 88.42,34.224 88.42,34.732 ; 88.42,34.732 pad.@88.42,35.24 ; 88.42,34.732 88.453,34.732 ; pad.@88.42,35.24 pad.@88.453,35.24 ; pad.@88.42,35.24 pad.@88.42,35.621 ; 88.453,20.889 88.453,21.016 ; 88.453,20.889 88.961,20.889 ; 88.453,21.016 88.453,21.524 ; 88.453,21.016 88.961,21.016 ; 88.453,21.524 88.453,22.032 ; 88.453,21.524 pad.@88.961,21.524 ; 88.453,22.032 CN2.5@88.453,22.54 ; 88.453,22.032 88.961,22.032 ; CN2.5@88.453,22.54 CN2.5@88.453,23.048 ; CN2.5@88.453,22.54 CN2.5@88.961,22.54 ; CN2.5@88.453,23.048 CN2.5@88.453,23.556 ; CN2.5@88.453,23.048 CN2.5@88.961,23.048 ; CN2.5@88.453,23.556 88.453,24.064 ; CN2.5@88.453,23.556 CN2.5@88.961,23.556 ; 88.453,24.064 88.453,24.572 ; 88.453,24.064 88.961,24.064 ; 88.453,24.572 88.453,25.08 ; 88.453,24.572 88.961,24.572 ; 88.453,25.08 pad.@88.453,25.588 ; 88.453,25.08 88.961,25.08 ; pad.@88.453,25.588 pad.@88.453,26.096 ; pad.@88.453,25.588 pad.@88.961,25.588 ; pad.@88.453,26.096 88.453,26.604 ; pad.@88.453,26.096 88.961,26.096 ; 88.453,26.604 88.453,27.112 ; 88.453,26.604 88.961,26.604 ; 88.453,27.112 88.453,27.62 ; 88.453,27.112 88.961,27.112 ; 88.453,27.62 88.453,28.128 ; 88.453,27.62 88.961,27.62 ; 88.453,28.128 pad.@88.453,28.636 ; 88.453,28.128 88.961,28.128 ; pad.@88.453,28.636 pad.@88.453,29.144 ; pad.@88.453,28.636 88.961,28.636 ; pad.@88.453,29.144 88.453,29.652 ; pad.@88.453,29.144 88.961,29.144 ; 88.453,29.652 88.453,30.16 ; 88.453,29.652 88.961,29.652 ; 88.453,30.16 88.453,30.668 ; 88.453,30.16 88.961,30.16 ; 88.453,30.668 88.453,31.176 ; 88.453,30.668 88.961,30.668 ; 88.453,31.176 88.453,31.684 ; 88.453,31.176 88.961,31.176 ; 88.453,31.684 88.453,32.192 ; 88.453,31.684 88.961,31.684 ; 88.453,32.192 88.453,32.7 ; 88.453,32.192 88.961,32.192 ; 88.453,32.7 88.453,33.208 ; 88.453,32.7 88.961,32.7 ; 88.453,33.208 pad.@88.453,33.716 ; 88.453,33.208 88.961,33.208 ; pad.@88.453,33.716 88.453,34.224 ; pad.@88.453,33.716 pad.@88.961,33.716 ; 88.453,34.224 88.453,34.732 ; 88.453,34.224 88.961,34.224 ; 88.453,34.732 pad.@88.453,35.24 ; 88.453,34.732 88.961,34.732 ; pad.@88.453,35.24 88.453,35.748 ; pad.@88.453,35.24 88.961,35.24 ; 88.453,35.748 88.453,36.256 ; 88.453,35.748 88.961,35.748 ; 88.453,36.256 pad.@88.453,36.764 ; 88.453,36.256 88.961,36.256 ; pad.@88.453,36.764 88.453,37.272 ; pad.@88.453,36.764 pad.@88.961,36.764 ; 88.453,37.272 pad.@88.453,37.78 ; 88.453,37.272 88.961,37.272 ; pad.@88.453,37.78 pad.@88.453,38.288 ; pad.@88.453,37.78 88.961,37.78 ; pad.@88.453,38.288 88.453,38.796 ; pad.@88.453,38.288 88.961,38.288 ; 88.453,38.796 88.453,39.304 ; 88.453,38.796 88.961,38.796 ; 88.453,39.304 88.453,39.812 ; 88.453,39.304 88.961,39.304 ; 88.453,39.812 88.453,40.32 ; 88.453,39.812 88.961,39.812 ; 88.453,40.32 88.453,40.828 ; 88.453,40.32 88.961,40.32 ; 88.453,40.828 88.453,41.336 ; 88.453,40.828 88.961,40.828 ; 88.453,41.336 88.453,41.844 ; 88.453,41.336 88.961,41.336 ; 88.453,41.844 88.453,42.352 ; 88.453,41.844 88.961,41.844 ; 88.453,42.352 88.453,42.86 ; 88.453,42.352 88.961,42.352 ; 88.453,42.86 88.453,43.368 ; 88.453,42.86 88.961,42.86 ; 88.453,43.368 88.453,43.876 ; 88.453,43.368 88.961,43.368 ; 88.453,43.876 88.453,44.384 ; 88.453,43.876 88.961,43.876 ; 88.453,44.384 88.453,44.892 ; 88.453,44.384 88.961,44.384 ; 88.453,44.892 88.453,45.4 ; 88.453,44.892 88.961,44.892 ; 88.453,45.4 88.453,45.908 ; 88.453,45.4 88.961,45.4 ; 88.453,45.908 88.453,46.416 ; 88.453,45.908 88.961,45.908 ; 88.453,46.416 88.453,46.924 ; 88.453,46.416 88.961,46.416 ; 88.453,46.924 88.453,47.432 ; 88.453,46.924 88.961,46.924 ; 88.453,47.432 88.453,47.94 ; 88.453,47.432 88.961,47.432 ; 88.453,47.94 88.453,48.448 ; 88.453,47.94 88.961,47.94 ; 88.453,48.448 88.453,48.956 ; 88.453,48.448 88.961,48.448 ; 88.453,48.956 88.453,49.464 ; 88.453,48.956 88.961,48.956 ; 88.453,49.464 88.453,49.972 ; 88.453,49.464 88.961,49.464 ; 88.453,49.972 88.453,50.48 ; 88.453,49.972 88.961,49.972 ; 88.453,50.48 88.453,50.988 ; 88.453,50.48 88.961,50.48 ; 88.453,50.988 88.453,51.496 ; 88.453,50.988 88.961,50.988 ; 88.453,51.496 88.453,52.004 ; 88.453,51.496 88.961,51.496 ; 88.453,52.004 88.453,52.512 ; 88.453,52.004 88.961,52.004 ; 88.453,52.512 88.453,53.02 ; 88.453,52.512 88.961,52.512 ; 88.453,53.02 88.453,53.528 ; 88.453,53.02 88.961,53.02 ; 88.453,53.528 88.453,54.036 ; 88.453,53.528 88.961,53.528 ; 88.453,54.036 88.453,54.544 ; 88.453,54.036 88.961,54.036 ; 88.453,54.544 88.453,55.052 ; 88.453,54.544 88.961,54.544 ; 88.453,55.052 88.453,55.56 ; 88.453,55.052 88.961,55.052 ; 88.453,55.56 88.453,56.068 ; 88.453,55.56 88.961,55.56 ; 88.453,56.068 88.453,56.576 ; 88.453,56.068 88.961,56.068 ; 88.453,56.576 88.453,57.084 ; 88.453,56.576 88.961,56.576 ; 88.453,57.084 88.453,57.592 ; 88.453,57.084 88.961,57.084 ; 88.453,57.592 88.453,58.1 ; 88.453,57.592 88.961,57.592 ; 88.453,58.1 88.453,58.608 ; 88.453,58.1 88.961,58.1 ; 88.453,58.608 88.453,59.116 ; 88.453,58.608 88.961,58.608 ; 88.453,59.116 88.453,59.624 ; 88.453,59.116 88.961,59.116 ; 88.453,59.624 88.453,60.132 ; 88.453,59.624 pad.@88.961,59.624 ; 88.453,60.132 88.961,60.132 ; 88.961,20.889 88.961,21.016 ; 88.961,20.889 89.342,20.889 89.551,21.098 89.723,21.27 89.723,21.524 ; 88.961,21.016 pad.@88.961,21.524 ; 88.961,21.016 89.469,21.016 pad.@89.469,21.524 ; pad.@88.961,21.524 88.961,22.032 ; pad.@88.961,21.524 pad.@89.469,21.524 ; 88.961,22.032 CN2.5@88.961,22.54 ; 88.961,22.032 89.469,22.032 ; CN2.5@88.961,22.54 CN2.5@88.961,23.048 ; CN2.5@88.961,22.54 89.469,22.54 ; CN2.5@88.961,23.048 89.469,23.048 ; CN2.5@88.961,23.048 CN2.5@88.961,23.556 ; CN2.5@88.961,23.556 88.961,24.064 ; CN2.5@88.961,23.556 89.469,23.556 ; 88.961,24.064 88.961,24.572 ; 88.961,24.064 89.469,24.064 ; 88.961,24.572 88.961,25.08 ; 88.961,24.572 89.469,24.572 ; 88.961,25.08 89.469,25.08 ; 88.961,25.08 pad.@88.961,25.588 ; pad.@88.961,25.588 89.469,25.588 ; pad.@88.961,25.588 88.961,26.096 ; 88.961,26.096 89.469,26.096 ; 88.961,26.096 88.961,26.604 ; 88.961,26.604 88.961,27.112 ; 88.961,26.604 89.469,26.604 ; 88.961,27.112 88.961,27.62 ; 88.961,27.112 89.469,27.112 ; 88.961,27.62 88.961,28.128 ; 88.961,27.62 89.469,27.62 ; 88.961,28.128 88.961,28.636 ; 88.961,28.128 89.469,28.128 ; 88.961,28.636 89.469,28.636 ; 88.961,28.636 88.961,29.144 ; 88.961,29.144 88.961,29.652 ; 88.961,29.144 89.469,29.144 ; 88.961,29.652 88.961,30.16 ; 88.961,29.652 89.469,29.652 ; 88.961,30.16 88.961,30.668 ; 88.961,30.16 89.469,30.16 ; 88.961,30.668 89.469,30.668 ; 88.961,30.668 88.961,31.176 ; 88.961,31.176 88.961,31.684 ; 88.961,31.176 89.469,31.176 ; 88.961,31.684 89.469,31.684 ; 88.961,31.684 88.961,32.192 ; 88.961,32.192 89.469,32.192 ; 88.961,32.192 88.961,32.7 ; 88.961,32.7 88.961,33.208 ; 88.961,32.7 89.469,32.7 ; 88.961,33.208 89.469,33.208 ; 88.961,33.208 pad.@88.961,33.716 ; pad.@88.961,33.716 88.961,34.224 ; pad.@88.961,33.716 89.469,33.716 ; 88.961,34.224 88.961,34.732 ; 88.961,34.224 89.469,34.224 ; 88.961,34.732 88.961,35.24 ; 88.961,34.732 89.469,34.732 ; 88.961,35.24 89.469,35.24 ; 88.961,35.24 88.961,35.748 ; 88.961,35.748 89.469,35.748 ; 88.961,35.748 88.961,36.256 ; 88.961,36.256 89.469,36.256 ; 88.961,36.256 pad.@88.961,36.764 ; pad.@88.961,36.764 89.469,36.764 ; pad.@88.961,36.764 88.961,37.272 ; 88.961,37.272 88.961,37.78 ; 88.961,37.272 89.469,37.272 ; 88.961,37.78 89.469,37.78 ; 88.961,37.78 88.961,38.288 ; 88.961,38.288 88.961,38.796 ; 88.961,38.288 89.469,38.288 ; 88.961,38.796 88.961,39.304 ; 88.961,38.796 89.469,38.796 ; 88.961,39.304 88.961,39.812 ; 88.961,39.304 89.469,39.304 ; 88.961,39.812 89.469,39.812 ; 88.961,39.812 88.961,40.32 ; 88.961,40.32 88.961,40.828 ; 88.961,40.32 89.469,40.32 ; 88.961,40.828 88.961,41.336 ; 88.961,40.828 89.469,40.828 ; 88.961,41.336 88.961,41.844 ; 88.961,41.336 89.469,41.336 ; 88.961,41.844 88.961,42.352 ; 88.961,41.844 89.469,41.844 ; 88.961,42.352 88.961,42.86 ; 88.961,42.352 89.469,42.352 ; 88.961,42.86 88.961,43.368 ; 88.961,42.86 89.469,42.86 ; 88.961,43.368 88.961,43.876 ; 88.961,43.368 89.469,43.368 ; 88.961,43.876 88.961,44.384 ; 88.961,43.876 89.469,43.876 ; 88.961,44.384 89.469,44.384 ; 88.961,44.384 88.961,44.892 ; 88.961,44.892 89.469,44.892 ; 88.961,44.892 88.961,45.4 ; 88.961,45.4 88.961,45.908 ; 88.961,45.4 89.469,45.4 ; 88.961,45.908 88.961,46.416 ; 88.961,45.908 89.469,45.908 ; 88.961,46.416 89.469,46.416 ; 88.961,46.416 88.961,46.924 ; 88.961,46.924 89.469,46.924 ; 88.961,46.924 88.961,47.432 ; 88.961,47.432 88.961,47.94 ; 88.961,47.432 89.469,47.432 ; 88.961,47.94 88.961,48.448 ; 88.961,47.94 89.469,47.94 ; 88.961,48.448 88.961,48.956 ; 88.961,48.448 89.469,48.448 ; 88.961,48.956 88.961,49.464 ; 88.961,48.956 89.469,48.956 ; 88.961,49.464 88.961,49.972 ; 88.961,49.464 89.469,49.464 ; 88.961,49.972 89.469,49.972 ; 88.961,49.972 88.961,50.48 ; 88.961,50.48 88.961,50.988 ; 88.961,50.48 89.469,50.48 ; 88.961,50.988 89.469,50.988 ; 88.961,50.988 88.961,51.496 ; 88.961,51.496 88.961,52.004 ; 88.961,51.496 89.469,51.496 ; 88.961,52.004 89.469,52.004 ; 88.961,52.004 88.961,52.512 ; 88.961,52.512 88.961,53.02 ; 88.961,52.512 89.469,52.512 ; 88.961,53.02 89.469,53.02 ; 88.961,53.02 88.961,53.528 ; 88.961,53.528 88.961,54.036 ; 88.961,53.528 89.469,53.528 ; 88.961,54.036 88.961,54.544 ; 88.961,54.036 89.469,54.036 ; 88.961,54.544 88.961,55.052 ; 88.961,54.544 89.469,54.544 ; 88.961,55.052 89.469,55.052 ; 88.961,55.052 88.961,55.56 ; 88.961,55.56 89.469,55.56 ; 88.961,55.56 88.961,56.068 ; 88.961,56.068 88.961,56.576 ; 88.961,56.068 89.469,56.068 ; 88.961,56.576 89.469,56.576 ; 88.961,56.576 88.961,57.084 ; 88.961,57.084 88.961,57.592 ; 88.961,57.084 89.469,57.084 ; 88.961,57.592 88.961,58.1 ; 88.961,57.592 89.469,57.592 ; 88.961,58.1 88.961,58.608 ; 88.961,58.1 89.469,58.1 ; 88.961,58.608 88.961,59.116 ; 88.961,58.608 89.469,58.608 ; 88.961,59.116 pad.@88.961,59.624 ; 88.961,59.116 89.469,59.116 ; pad.@88.961,59.624 88.961,60.132 ; pad.@88.961,59.624 89.469,59.624 ; 88.961,60.132 89.469,60.132 ; pad.@89.469,21.524 89.469,22.032 ; pad.@89.469,21.524 89.723,21.524 ; 89.469,22.032 89.469,22.54 ; 89.469,22.032 89.723,22.032 ; 89.469,22.54 89.469,23.048 ; 89.469,22.54 89.723,22.54 ; 89.469,23.048 89.723,23.048 ; 89.469,23.048 89.469,23.556 ; 89.469,23.556 89.469,24.064 ; 89.469,23.556 89.723,23.556 ; 89.469,24.064 89.469,24.572 ; 89.469,24.064 89.723,24.064 ; 89.469,24.572 89.469,25.08 ; 89.469,24.572 89.723,24.572 ; 89.469,25.08 89.723,25.08 ; 89.469,25.08 89.469,25.588 ; 89.469,25.588 89.469,26.096 ; 89.469,25.588 89.723,25.588 ; 89.469,26.096 89.469,26.604 ; 89.469,26.096 89.723,26.096 ; 89.469,26.604 89.469,27.112 ; 89.469,26.604 89.723,26.604 ; 89.469,27.112 89.469,27.62 ; 89.469,27.112 89.723,27.112 ; 89.469,27.62 89.469,28.128 ; 89.469,27.62 89.723,27.62 ; 89.469,28.128 89.469,28.636 ; 89.469,28.128 89.723,28.128 ; 89.469,28.636 89.469,29.144 ; 89.469,28.636 89.723,28.636 ; 89.469,29.144 89.469,29.652 ; 89.469,29.144 89.723,29.144 ; 89.469,29.652 89.469,30.16 ; 89.469,29.652 89.723,29.652 ; 89.469,30.16 89.469,30.668 ; 89.469,30.16 89.723,30.16 ; 89.469,30.668 89.469,31.176 ; 89.469,30.668 89.723,30.668 ; 89.469,31.176 89.469,31.684 ; 89.469,31.176 89.723,31.176 ; 89.469,31.684 89.469,32.192 ; 89.469,31.684 89.723,31.684 ; 89.469,32.192 89.469,32.7 ; 89.469,32.192 89.723,32.192 ; 89.469,32.7 89.469,33.208 ; 89.469,32.7 89.723,32.7 ; 89.469,33.208 89.469,33.716 ; 89.469,33.208 89.723,33.208 ; 89.469,33.716 89.469,34.224 ; 89.469,33.716 89.723,33.716 ; 89.469,34.224 89.469,34.732 ; 89.469,34.224 89.723,34.224 ; 89.469,34.732 89.469,35.24 ; 89.469,34.732 89.723,34.732 ; 89.469,35.24 89.469,35.748 ; 89.469,35.24 89.723,35.24 ; 89.469,35.748 89.469,36.256 ; 89.469,35.748 89.723,35.748 ; 89.469,36.256 89.469,36.764 ; 89.469,36.256 89.723,36.256 ; 89.469,36.764 89.469,37.272 ; 89.469,36.764 89.723,36.764 ; 89.469,37.272 89.469,37.78 ; 89.469,37.272 89.723,37.272 ; 89.469,37.78 89.469,38.288 ; 89.469,37.78 89.723,37.78 ; 89.469,38.288 89.469,38.796 ; 89.469,38.288 89.723,38.288 ; 89.469,38.796 89.469,39.304 ; 89.469,38.796 89.723,38.796 ; 89.469,39.304 89.469,39.812 ; 89.469,39.304 89.723,39.304 ; 89.469,39.812 89.469,40.32 ; 89.469,39.812 89.723,39.812 ; 89.469,40.32 89.469,40.828 ; 89.469,40.32 89.723,40.32 ; 89.469,40.828 89.469,41.336 ; 89.469,40.828 89.723,40.828 ; 89.469,41.336 89.469,41.844 ; 89.469,41.336 89.977,41.336 ; 89.469,41.844 89.469,42.352 ; 89.469,41.844 89.977,41.844 ; 89.469,42.352 89.469,42.86 ; 89.469,42.352 89.977,42.352 ; 89.469,42.86 89.469,43.368 ; 89.469,42.86 89.977,42.86 ; 89.469,43.368 89.469,43.876 ; 89.469,43.368 89.977,43.368 ; 89.469,43.876 89.469,44.384 ; 89.469,43.876 89.977,43.876 ; 89.469,44.384 89.977,44.384 ; 89.469,44.384 89.469,44.892 ; 89.469,44.892 89.977,44.892 ; 89.469,44.892 89.469,45.4 ; 89.469,45.4 89.469,45.908 ; 89.469,45.4 89.977,45.4 ; 89.469,45.908 89.469,46.416 ; 89.469,45.908 89.977,45.908 ; 89.469,46.416 89.469,46.924 ; 89.469,46.416 89.977,46.416 ; 89.469,46.924 89.469,47.432 ; 89.469,46.924 89.977,46.924 ; 89.469,47.432 89.469,47.94 ; 89.469,47.432 89.977,47.432 ; 89.469,47.94 89.469,48.448 ; 89.469,47.94 89.977,47.94 ; 89.469,48.448 89.469,48.956 ; 89.469,48.448 89.977,48.448 ; 89.469,48.956 89.469,49.464 ; 89.469,48.956 89.977,48.956 ; 89.469,49.464 89.469,49.972 ; 89.469,49.464 89.977,49.464 ; 89.469,49.972 89.977,49.972 ; 89.469,49.972 89.469,50.48 ; 89.469,50.48 89.469,50.988 ; 89.469,50.48 89.977,50.48 ; 89.469,50.988 89.977,50.988 ; 89.469,50.988 89.469,51.496 ; 89.469,51.496 89.469,52.004 ; 89.469,51.496 89.977,51.496 ; 89.469,52.004 89.977,52.004 ; 89.469,52.004 89.469,52.512 ; 89.469,52.512 89.469,53.02 ; 89.469,52.512 89.977,52.512 ; 89.469,53.02 89.469,53.528 ; 89.469,53.02 89.977,53.02 ; 89.469,53.528 89.469,54.036 ; 89.469,53.528 89.977,53.528 ; 89.469,54.036 89.469,54.544 ; 89.469,54.036 89.977,54.036 ; 89.469,54.544 89.469,55.052 ; 89.469,54.544 89.977,54.544 ; 89.469,55.052 89.469,55.56 ; 89.469,55.052 89.977,55.052 ; 89.469,55.56 89.469,56.068 ; 89.469,55.56 89.977,55.56 ; 89.469,56.068 89.469,56.576 ; 89.469,56.068 89.977,56.068 ; 89.469,56.576 89.469,57.084 ; 89.469,56.576 89.977,56.576 ; 89.469,57.084 89.469,57.592 ; 89.469,57.084 89.977,57.084 ; 89.469,57.592 89.469,58.1 ; 89.469,57.592 89.977,57.592 ; 89.469,58.1 89.469,58.608 ; 89.469,58.1 89.977,58.1 ; 89.469,58.608 89.469,59.116 ; 89.469,58.608 89.977,58.608 ; 89.469,59.116 89.977,59.116 ; 89.469,59.116 89.469,59.624 ; 89.469,59.624 89.977,59.624 ; 89.469,59.624 89.469,60.132 ; 89.723,21.524 89.723,22.032 ; 89.723,22.032 89.723,22.54 ; 89.723,22.54 89.723,23.048 ; 89.723,23.048 89.723,23.556 ; 89.723,23.556 89.723,24.064 ; 89.723,24.064 89.723,24.572 ; 89.723,24.572 89.723,25.08 ; 89.723,25.08 89.723,25.588 ; 89.723,25.588 89.723,26.096 ; 89.723,26.096 89.723,26.604 ; 89.723,26.604 89.723,27.112 ; 89.723,27.112 89.723,27.62 ; 89.723,27.62 89.723,28.128 ; 89.723,28.128 89.723,28.636 ; 89.723,28.636 89.723,29.144 ; 89.723,29.144 89.723,29.652 ; 89.723,29.652 89.723,30.16 ; 89.723,30.16 89.723,30.668 ; 89.723,30.668 89.723,31.176 ; 89.723,31.176 89.723,31.684 ; 89.723,31.684 89.723,32.192 ; 89.723,32.192 89.723,32.7 ; 89.723,32.7 89.723,33.208 ; 89.723,33.208 89.723,33.716 ; 89.723,33.716 89.723,34.224 ; 89.723,34.224 89.723,34.732 ; 89.723,34.732 89.723,35.24 ; 89.723,35.24 89.723,35.748 ; 89.723,35.748 89.723,36.256 ; 89.723,36.256 89.723,36.764 ; 89.723,36.764 89.723,37.272 ; 89.723,37.272 89.723,37.78 ; 89.723,37.78 89.723,38.288 ; 89.723,38.288 89.723,38.796 ; 89.723,38.796 89.723,39.304 ; 89.723,39.304 89.723,39.812 ; 89.723,39.812 89.723,40.32 ; 89.723,40.32 89.723,40.828 ; 89.723,40.828 89.977,41.082 ; 89.899,59.715 cw(c90.773,60.59) 89.644,60.087 ccw(c90.773,60.59) 89.899,59.715 ; 89.899,59.715 89.977,59.637 ; 89.977,41.082 90.231,41.336 ; 89.977,41.082 89.977,41.336 ; 89.977,41.336 89.977,41.844 ; 89.977,41.336 90.231,41.336 ; 89.977,41.844 89.977,42.352 ; 89.977,41.844 90.485,41.844 ; 89.977,42.352 89.977,42.86 ; 89.977,42.352 90.485,42.352 ; 89.977,42.86 89.977,43.368 ; 89.977,42.86 90.485,42.86 ; 89.977,43.368 89.977,43.876 ; 89.977,43.368 90.485,43.368 ; 89.977,43.876 89.977,44.384 ; 89.977,43.876 90.485,43.876 ; 89.977,44.384 90.485,44.384 ; 89.977,44.384 89.977,44.892 ; 89.977,44.892 90.485,44.892 ; 89.977,44.892 89.977,45.4 ; 89.977,45.4 89.977,45.908 ; 89.977,45.4 90.485,45.4 ; 89.977,45.908 89.977,46.416 ; 89.977,45.908 90.485,45.908 ; 89.977,46.416 89.977,46.924 ; 89.977,46.416 90.485,46.416 ; 89.977,46.924 89.977,47.432 ; 89.977,46.924 90.485,46.924 ; 89.977,47.432 89.977,47.94 ; 89.977,47.432 90.485,47.432 ; 89.977,47.94 89.977,48.448 ; 89.977,47.94 90.485,47.94 ; 89.977,48.448 89.977,48.956 ; 89.977,48.448 90.485,48.448 ; 89.977,48.956 89.977,49.464 ; 89.977,48.956 90.485,48.956 ; 89.977,49.464 89.977,49.972 ; 89.977,49.464 90.485,49.464 ; 89.977,49.972 90.485,49.972 ; 89.977,49.972 89.977,50.48 ; 89.977,50.48 89.977,50.988 ; 89.977,50.48 90.485,50.48 ; 89.977,50.988 90.485,50.988 ; 89.977,50.988 89.977,51.496 ; 89.977,51.496 89.977,52.004 ; 89.977,51.496 90.485,51.496 ; 89.977,52.004 90.485,52.004 ; 89.977,52.004 89.977,52.512 ; 89.977,52.512 89.977,53.02 ; 89.977,52.512 90.485,52.512 ; 89.977,53.02 89.977,53.528 ; 89.977,53.02 90.485,53.02 ; 89.977,53.528 89.977,54.036 ; 89.977,53.528 90.485,53.528 ; 89.977,54.036 89.977,54.544 ; 89.977,54.036 90.485,54.036 ; 89.977,54.544 89.977,55.052 ; 89.977,54.544 90.485,54.544 ; 89.977,55.052 89.977,55.56 ; 89.977,55.052 90.485,55.052 ; 89.977,55.56 89.977,56.068 ; 89.977,55.56 90.485,55.56 ; 89.977,56.068 89.977,56.576 ; 89.977,56.068 90.485,56.068 ; 89.977,56.576 89.977,57.084 ; 89.977,56.576 90.485,56.576 ; 89.977,57.084 89.977,57.592 ; 89.977,57.084 90.485,57.084 ; 89.977,57.592 89.977,58.1 ; 89.977,57.592 90.485,57.592 ; 89.977,58.1 89.977,58.608 ; 89.977,58.1 90.485,58.1 ; 89.977,58.608 89.977,59.116 ; 89.977,58.608 90.485,58.608 ; 89.977,59.116 90.485,59.116 ; 89.977,59.116 89.977,59.624 ; 89.977,59.624 89.99,59.624 ; 89.977,59.624 89.977,59.637 ; 89.977,59.637 89.99,59.624 ; 89.99,59.624 90.485,59.129 ; 90.231,41.336 90.485,41.59 ; 90.485,41.59 90.739,41.844 ; 90.485,41.59 90.485,41.844 ; 90.485,41.844 90.485,42.352 ; 90.485,41.844 90.739,41.844 ; 90.485,42.352 90.485,42.86 ; 90.485,42.352 90.993,42.352 ; 90.485,42.86 90.485,43.368 ; 90.485,42.86 90.993,42.86 ; 90.485,43.368 90.485,43.876 ; 90.485,43.368 90.993,43.368 ; 90.485,43.876 90.485,44.384 ; 90.485,43.876 90.993,43.876 ; 90.485,44.384 90.993,44.384 ; 90.485,44.384 90.485,44.892 ; 90.485,44.892 90.993,44.892 ; 90.485,44.892 90.485,45.4 ; 90.485,45.4 90.485,45.908 ; 90.485,45.4 90.993,45.4 ; 90.485,45.908 90.485,46.416 ; 90.485,45.908 90.993,45.908 ; 90.485,46.416 90.485,46.924 ; 90.485,46.416 90.993,46.416 ; 90.485,46.924 90.485,47.432 ; 90.485,46.924 90.993,46.924 ; 90.485,47.432 90.485,47.94 ; 90.485,47.432 90.993,47.432 ; 90.485,47.94 90.485,48.448 ; 90.485,47.94 90.993,47.94 ; 90.485,48.448 90.485,48.956 ; 90.485,48.448 90.993,48.448 ; 90.485,48.956 90.485,49.464 ; 90.485,48.956 90.993,48.956 ; 90.485,49.464 90.485,49.972 ; 90.485,49.464 90.993,49.464 ; 90.485,49.972 90.993,49.972 ; 90.485,49.972 90.485,50.48 ; 90.485,50.48 90.485,50.988 ; 90.485,50.48 90.993,50.48 ; 90.485,50.988 90.993,50.988 ; 90.485,50.988 90.485,51.496 ; 90.485,51.496 90.485,52.004 ; 90.485,51.496 90.993,51.496 ; 90.485,52.004 90.993,52.004 ; 90.485,52.004 90.485,52.512 ; 90.485,52.512 90.485,53.02 ; 90.485,52.512 90.993,52.512 ; 90.485,53.02 90.485,53.528 ; 90.485,53.02 90.993,53.02 ; 90.485,53.528 90.485,54.036 ; 90.485,53.528 90.993,53.528 ; 90.485,54.036 90.485,54.544 ; 90.485,54.036 90.993,54.036 ; 90.485,54.544 90.485,55.052 ; 90.485,54.544 90.993,54.544 ; 90.485,55.052 90.485,55.56 ; 90.485,55.052 90.993,55.052 ; 90.485,55.56 90.485,56.068 ; 90.485,55.56 90.993,55.56 ; 90.485,56.068 90.485,56.576 ; 90.485,56.068 90.993,56.068 ; 90.485,56.576 90.485,57.084 ; 90.485,56.576 90.993,56.576 ; 90.485,57.084 90.485,57.592 ; 90.485,57.084 90.993,57.084 ; 90.485,57.592 90.485,58.1 ; 90.485,57.592 90.993,57.592 ; 90.485,58.1 90.485,58.608 ; 90.485,58.1 90.993,58.1 ; 90.485,58.608 90.485,59.116 ; 90.485,58.608 90.993,58.608 ; 90.485,59.116 90.485,59.129 ; 90.485,59.116 90.498,59.116 ; 90.485,59.129 90.498,59.116 ; 90.498,59.116 90.993,58.621 ; 90.739,41.844 90.993,42.098 ; 90.993,42.098 90.993,42.352 ; 90.993,42.098 91.247,42.352 ; 90.993,42.352 90.993,42.86 ; 90.993,42.352 91.247,42.352 ; 90.993,42.86 90.993,43.368 ; 90.993,42.86 91.501,42.86 ; 90.993,43.368 90.993,43.876 ; 90.993,43.368 91.501,43.368 ; 90.993,43.876 90.993,44.384 ; 90.993,43.876 91.501,43.876 ; 90.993,44.384 90.993,44.892 ; 90.993,44.384 91.501,44.384 ; 90.993,44.892 90.993,45.4 ; 90.993,44.892 91.501,44.892 ; 90.993,45.4 90.993,45.908 ; 90.993,45.4 91.501,45.4 ; 90.993,45.908 90.993,46.416 ; 90.993,45.908 91.501,45.908 ; 90.993,46.416 90.993,46.924 ; 90.993,46.416 91.501,46.416 ; 90.993,46.924 90.993,47.432 ; 90.993,46.924 91.501,46.924 ; 90.993,47.432 90.993,47.94 ; 90.993,47.432 91.501,47.432 ; 90.993,47.94 90.993,48.448 ; 90.993,47.94 91.501,47.94 ; 90.993,48.448 90.993,48.956 ; 90.993,48.448 91.501,48.448 ; 90.993,48.956 90.993,49.464 ; 90.993,48.956 91.501,48.956 ; 90.993,49.464 90.993,49.972 ; 90.993,49.464 91.501,49.464 ; 90.993,49.972 90.993,50.48 ; 90.993,49.972 91.501,49.972 ; 90.993,50.48 90.993,50.988 ; 90.993,50.48 91.501,50.48 ; 90.993,50.988 90.993,51.496 ; 90.993,50.988 91.501,50.988 ; 90.993,51.496 90.993,52.004 ; 90.993,51.496 91.501,51.496 ; 90.993,52.004 90.993,52.512 ; 90.993,52.004 91.501,52.004 ; 90.993,52.512 90.993,53.02 ; 90.993,52.512 91.501,52.512 ; 90.993,53.02 90.993,53.528 ; 90.993,53.02 91.501,53.02 ; 90.993,53.528 90.993,54.036 ; 90.993,53.528 91.501,53.528 ; 90.993,54.036 90.993,54.544 ; 90.993,54.036 91.501,54.036 ; 90.993,54.544 90.993,55.052 ; 90.993,54.544 91.501,54.544 ; 90.993,55.052 90.993,55.56 ; 90.993,55.052 91.501,55.052 ; 90.993,55.56 90.993,56.068 ; 90.993,55.56 91.501,55.56 ; 90.993,56.068 90.993,56.576 ; 90.993,56.068 91.501,56.068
